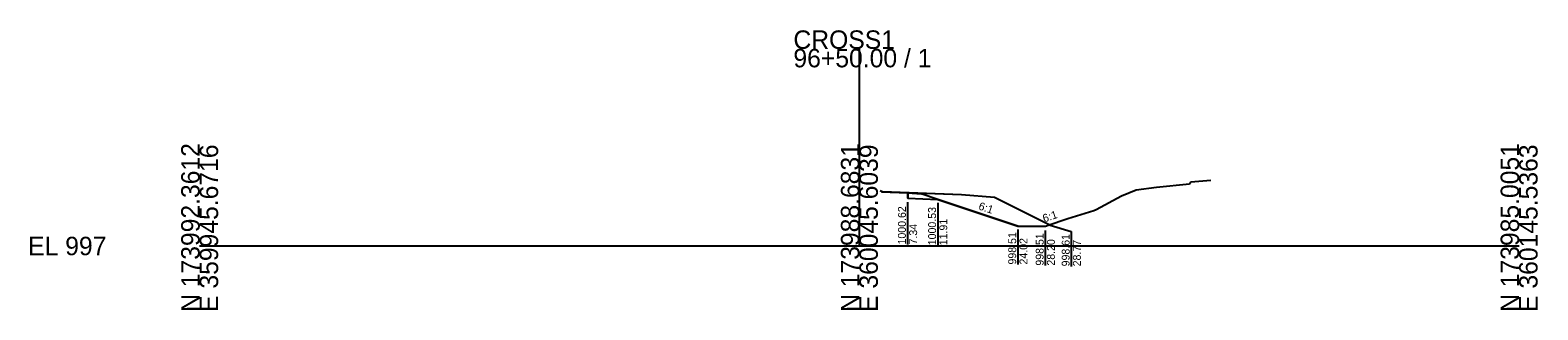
# Model space of a CAD drawing. Extents: x -26 to 1403, y -10 to 11027.
# Drawn here: x 1174.3 to 1402.8, y -9.7 to 32.8 of the extents above; entities that cross this region are included whole.
import ezdxf

# ---------------------------------------------------------------- set-up
doc = ezdxf.new("R2010")
doc.units = 0
for name, color, linetype in [('Default', 7, 'Continuous'), ('P_E_XS_Ground', 7, 'Continuous'), ('P_XS', 7, 'Continuous'), ('P_XS_EAR_CommonGrnd', 7, 'Continuous'), ('P_XS_Lane', 7, 'Continuous'), ('P_XS_Rock', 7, 'Continuous')]:
    doc.layers.add(name, color=color, linetype=linetype)

msp = doc.modelspace()

# ---------------------------------------------------------------- linework, layer by layer
at = {"layer": 'Default'}
for p, q in [((1300, 0), (1300, 29.91)), ((1200, 0), (1300, 0)), ((1300, 0), (1400, 0))]:
    msp.add_line(p, q, dxfattribs=at)
at = {"layer": 'P_E_XS_Ground'}
for p, q in [((1345.02, 8.9), (1350.05, 9.45)), ((1350.05, 9.45), (1350.23, 9.74)), ((1350.23, 9.74), (1353.28, 9.97)), ((1303.17, 8.4), (1303.57, 8.23)), ((1315.5, 7.75), (1303.57, 8.23)), ((1320.5, 7.35), (1315.5, 7.75)), ((1328.77, 3.22), (1320.5, 7.35)), ((1335.88, 5.53), (1339.73, 7.59)), ((1339.73, 7.59), (1341.95, 8.54)), ((1341.95, 8.54), (1345.02, 8.9)), ((1331.62, 4.16), (1335.52, 5.39)), ((1335.52, 5.39), (1335.88, 5.53)), ((1328.77, 3.22), (1331.29, 4.05)), ((1331.29, 4.05), (1331.62, 4.16))]:
    msp.add_line(p, q, dxfattribs=at)
at = {"layer": 'P_XS'}
for p, q in [((1303.34, 8.24), (1307.34, 8.08)), ((1307.34, 8.08), (1309.34, 7.92)), ((1311.91, 7.06), (1309.34, 7.92))]:
    msp.add_line(p, q, dxfattribs=at)
at = {"layer": 'P_XS_EAR_CommonGrnd'}
msp.add_lwpolyline([(1320.5, 7.35), (1315.5, 7.75), (1307.34, 8.08), (1307.34, 7.25), (1311.91, 7.06), (1324.02, 3.03), (1328.2, 3.03), (1328.77, 3.22)], close=True, dxfattribs=at)
at = {"layer": 'P_XS_Lane'}
for p, q in [((1307.34, 7.25), (1307.34, 8.08)), ((1307.34, 7.25), (1311.91, 7.06)), ((1324.02, 3.03), (1311.91, 7.06)), ((1324.02, 3.03), (1328.2, 3.03)), ((1328.2, 3.03), (1328.77, 3.22))]:
    msp.add_line(p, q, dxfattribs=at)
at = {"layer": 'P_XS_Rock'}
for p, q in [((1307.3, 6.67), (1307.3, 0.23)), ((1311.87, 6.55), (1311.87, 0.11)), ((1324.02, 2.5), (1324.02, -2.81)), ((1328.18, 2.33), (1328.18, -2.98)), ((1328.94, 3.17), (1332.12, 2.22)), ((1332.12, 2.22), (1332.12, -3.09))]:
    msp.add_line(p, q, dxfattribs=at)

# ---------------------------------------------------------------- texts
at = {"layer": 'Default'}
for s, p in [('CROSS1', (1290, 29.91)), ('96+50.00 / 1', (1290, 27.11)), ('EL 997', (1174, -1.4))]:
    msp.add_text(s, height=2.8, dxfattribs=at).set_placement(p)
for s, p in [('N 173992.3612', (1200, -10)), ('E 359945.6716', (1202.8, -10)), ('N 173988.6831', (1300, -10)), ('E 360045.6039', (1302.8, -10)), ('N 173985.0051', (1400, -10)), ('E 360145.5363', (1402.8, -10))]:
    msp.add_text(s, height=2.8, rotation=90, dxfattribs=at).set_placement(p)
at = {"layer": 'P_XS_Rock'}
for s, rotation, p in [('1000.62', 90, (1307.05, 0.23)), ('1000.53', 90, (1311.62, 0.11)), ('6:1', 341.5651, (1317.96, 5.57)), ('6:1', 18.4349, (1328.01, 3.57)), ('7.34', 90, (1308.75, 0.23)), ('11.91', 90, (1313.32, 0.11)), ('998.51', 90, (1323.77, -2.81)), ('24.02', 90, (1325.47, -2.81)), ('998.51', 90, (1327.93, -2.98)), ('28.20', 90, (1329.63, -2.98)), ('998.61', 90, (1331.87, -3.09)), ('28.77', 90, (1333.57, -3.09))]:
    msp.add_text(s, height=1.2, rotation=rotation, dxfattribs=at).set_placement(p)

doc.saveas('drawing.dxf')
